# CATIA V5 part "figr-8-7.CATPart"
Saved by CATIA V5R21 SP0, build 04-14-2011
Part number: Part1
Bounding box of the stored display mesh (mm): x 4.549 to 89.781, y -52.238 to 26.36, z 54 to 147.773
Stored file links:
  D:\CATIA V5R21 E-RESOURCES\CATIA-V5R21\catia-v5r21-prt\c08-catia-v5r20-prt\c08-catia-v5r21-figr-8-7.CATPart
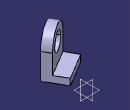
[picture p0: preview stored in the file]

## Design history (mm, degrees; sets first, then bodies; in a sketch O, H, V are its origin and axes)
Body1 (main body)
  Sketch1 on yz-plane, origin (0, 0, 0), H (0, 1, 0), V (0, 0, 1)
    point P1 (-104.4861, 0)
    line L1 (-104.4861, 0) -> (-104.4861, 44.267)
    arc A1 centre (-69.7903, 44.267) radius 34.6958 from (-104.4861, 44.267) to (-35.0946, 44.267) cw
    line L2 (-35.0946, 44.267) -> (-35.0946, 0)
    point P5 (-35.0946, 0)
    line L3 (-35.0946, 0) -> (-104.4861, 0)
    circle A2 centre (-69.7903, 44.267) radius 19.5413
    coincidence: P1 H, P5 H
    vertical: L1 V
    tangency: A1 L1, L2 A1
    horizontal: L3 H
  Pad1: profile Sketch1, direction (1, 0, 0), length 20
  Sketch2 on face of Pad1, origin (0, 0, 0), H (0, -1, 0), V (0, 0, 1)
    point P1 (35.0946, 0)
    line L1 (35.0946, 0) -> (104.4861, 0)
    line L2 (104.4861, 0) -> (104.4861, -15)
    line L3 (104.4861, -15) -> (35.0946, -15)
    line L4 (35.0946, -15) -> (35.0946, 0)
    reference projected line E1 (35.0946, 0) -> (35.0946, 44.267) from edge [face of Pad1 | face of Pad1]
    reference projected line E2 (104.4861, 44.267) -> (104.4861, 0) from edge [face of Pad1 | face of Pad1]
    distance L3 L1 = 15
    coincidence: P1 H, L4 E1, L2 E2
    horizontal: L1 H, L3 H
    vertical: L2 V, L4 V
  Pad2: profile Sketch2, direction (1, 0, 0), length 50
  Translate1: ToTransfor Pad2, Direction xy-plane, Length 69
  Rotate1: ToTransfor Translate1, Axis edge, Angle 121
